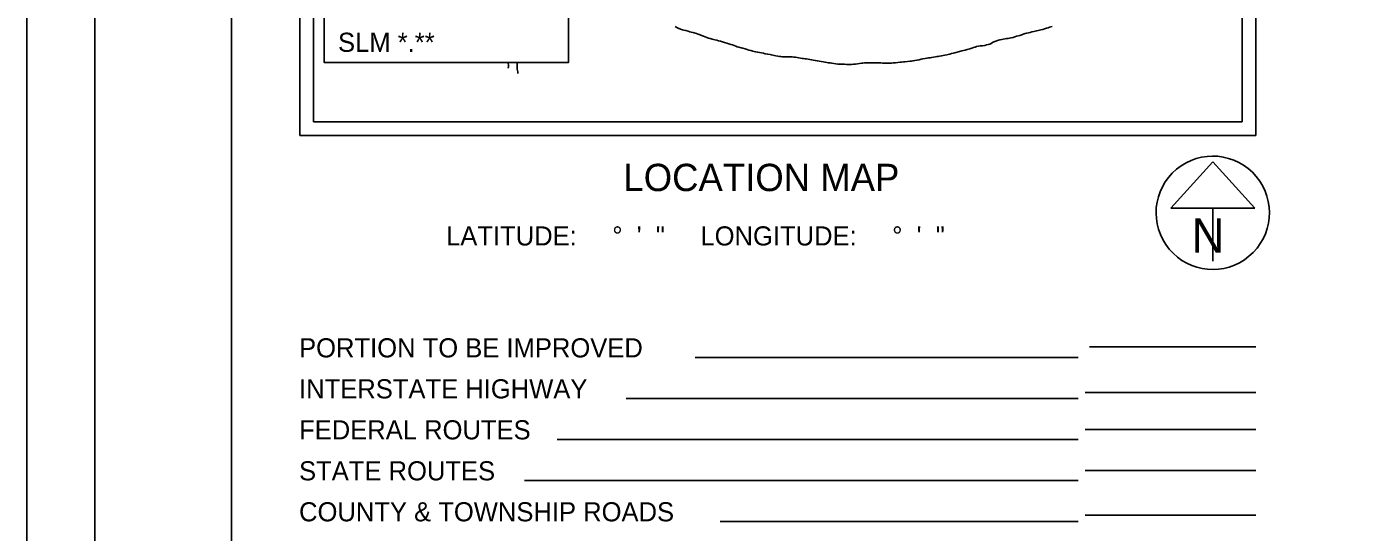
# Model space of a CAD drawing. Extents: x 0 to 34, y 0 to 22.
# Drawn here: x 0 to 9.77, y 11.1 to 14.8 of the extents above; entities that cross this region are included whole.
import ezdxf

# ---------------------------------------------------------------- set-up
doc = ezdxf.new("R2010")
doc.units = 0
for name, color, linetype in [('GM_X_Major_River', 7, 'Continuous'), ('SH_Border', 7, 'Continuous'), ('SH_Cut_Line', 7, 'Continuous'), ('SH_Data', 7, 'Continuous'), ('SH_Text', 7, 'Continuous')]:
    doc.layers.add(name, color=color, linetype=linetype)

msp = doc.modelspace()

# ---------------------------------------------------------------- linework, layer by layer
at = {"layer": 'GM_X_Major_River'}
for points in [[(4.7482, 14.7976), (4.761, 14.7915), (4.7709, 14.7874), (4.7871, 14.7801)], [(4.7871, 14.7801), (4.8015, 14.7748), (4.8121, 14.7718), (4.8261, 14.7684), (4.8423, 14.7638), (4.8556, 14.7604), (4.8666, 14.7578), (4.8783, 14.7551), (4.8885, 14.7513), (4.9036, 14.7464), (4.9172, 14.7419), (4.9316, 14.7377), (4.9414, 14.7331), (4.955, 14.7286), (4.969, 14.7233), (4.9804, 14.7187), (4.9929, 14.7142), (5.0057, 14.7096), (5.0182, 14.7058), (5.0292, 14.7028), (5.0398, 14.7001), (5.0522, 14.6975), (5.0647, 14.6945), (5.0795, 14.6907), (5.095, 14.6861), (5.1101, 14.682), (5.1275, 14.6774), (5.14, 14.6725), (5.1551, 14.6672), (5.168, 14.6634), (5.1812, 14.6596), (5.1922, 14.6547), (5.202, 14.6509), (5.2137, 14.6475), (5.2311, 14.6429), (5.2436, 14.6395), (5.2599, 14.6349), (5.2757, 14.6296), (5.2886, 14.6255), (5.3011, 14.6228), (5.3162, 14.6183), (5.3268, 14.6156), (5.3389, 14.6129), (5.3518, 14.6111), (5.3669, 14.608), (5.3813, 14.6057), (5.3941, 14.6031), (5.4077, 14.5993), (5.4259, 14.5955), (5.4429, 14.5925), (5.4535, 14.5902), (5.4645, 14.5879), (5.4747, 14.5856), (5.4849, 14.5841), (5.5008, 14.5811), (5.5121, 14.5792), (5.5231, 14.5781), (5.5329, 14.5773), (5.5443, 14.5769), (5.5567, 14.5762), (5.5681, 14.5762), (5.5783, 14.5754), (5.6044, 14.5754), (5.6173, 14.575), (5.6297, 14.5743), (5.6415, 14.5724), (5.6528, 14.5697), (5.6653, 14.5674), (5.6785, 14.5652), (5.6891, 14.564), (5.7012, 14.5625), (5.711, 14.5617), (5.7209, 14.5602), (5.7466, 14.5557), (5.7598, 14.5526), (5.7742, 14.5504), (5.7897, 14.5469), (5.8037, 14.5439), (5.8185, 14.5416), (5.8332, 14.5397), (5.8445, 14.5382), (5.8589, 14.5352), (5.8695, 14.5333), (5.8831, 14.5318), (5.8945, 14.5295), (5.9236, 14.5253), (5.9398, 14.5238), (5.9576, 14.5223), (5.9731, 14.5219), (5.9879, 14.5219), (6.0026, 14.5215), (6.0136, 14.5207), (6.0242, 14.5207), (6.0382, 14.5215), (6.0537, 14.5226), (6.0684, 14.5238), (6.0839, 14.5253), (6.0987, 14.5276), (6.1119, 14.5294), (6.1229, 14.531), (6.1342, 14.5321)], [(6.1342, 14.5321), (6.1444, 14.5329), (6.1679, 14.5336), (6.1826, 14.5336), (6.1981, 14.5332), (6.208, 14.5328), (6.2178, 14.5325), (6.2284, 14.5321), (6.2401, 14.5321), (6.2534, 14.5317), (6.2658, 14.5313), (6.2817, 14.5309), (6.2931, 14.5302), (6.3071, 14.5298), (6.3195, 14.5301), (6.3313, 14.5309), (6.3445, 14.532), (6.3611, 14.5332), (6.3785, 14.5351), (6.3948, 14.5366), (6.4065, 14.5381), (6.4198, 14.5392), (6.4303, 14.5404), (6.4496, 14.5422), (6.4685, 14.5441), (6.4791, 14.5449), (6.4893, 14.5464), (6.5026, 14.5491), (6.5181, 14.5517), (6.5347, 14.5555), (6.5502, 14.5597), (6.5616, 14.5623), (6.5778, 14.5642), (6.5911, 14.5665), (6.602, 14.5684), (6.6145, 14.5699), (6.6259, 14.5714), (6.6387, 14.5737), (6.6542, 14.5759), (6.6652, 14.5782), (6.675, 14.5793), (6.6849, 14.5816), (6.6992, 14.5839), (6.7106, 14.5862), (6.7227, 14.5884), (6.7363, 14.5911), (6.748, 14.5941), (6.7597, 14.596), (6.7722, 14.6002), (6.7843, 14.6024), (6.7949, 14.6058), (6.8123, 14.6104), (6.8305, 14.6153), (6.8482, 14.6202), (6.8607, 14.6233), (6.8724, 14.6259), (6.8868, 14.6297), (6.905, 14.6346), (6.9212, 14.6396), (6.9337, 14.6445), (6.9439, 14.6479), (6.9545, 14.6513), (6.9681, 14.6543), (6.9806, 14.657), (6.9987, 14.6581), (7.015, 14.6604), (7.029, 14.6634), (7.0411, 14.6657), (7.0524, 14.6699), (7.0623, 14.674), (7.0721, 14.6812), (7.0819, 14.6861), (7.0956, 14.6922), (7.1077, 14.6971), (7.1247, 14.7017), (7.1391, 14.704), (7.1508, 14.7058), (7.164, 14.7077), (7.1746, 14.71), (7.1875, 14.7119), (7.2071, 14.7149), (7.2234, 14.7187), (7.2359, 14.7229), (7.248, 14.7267), (7.2616, 14.7301), (7.2718, 14.7339), (7.2854, 14.738), (7.2956, 14.7414), (7.3111, 14.7464), (7.3228, 14.7502), (7.3357, 14.7528), (7.3467, 14.7555), (7.3603, 14.7585), (7.3735, 14.7611), (7.3841, 14.7642), (7.3951, 14.7664), (7.4068, 14.7691), (7.4257, 14.7733), (7.4401, 14.7778), (7.4533, 14.7827), (7.4662, 14.7861)], [(7.4662, 14.7861), (7.479, 14.7892), (7.4904, 14.793), (7.5082, 14.7986)], [(3.5253, 14.5355), (3.5259, 14.5299), (3.5274, 14.5144), (3.5274, 14.5049), (3.5263, 14.4943)], [(3.5958, 14.4552), (3.5951, 14.4658), (3.5939, 14.4757), (3.5921, 14.4859), (3.5902, 14.4992), (3.5909, 14.5121), (3.5921, 14.5261), (3.5937, 14.5355)]]:
    msp.add_lwpolyline(points, dxfattribs=at)
at = {"layer": 'SH_Border'}
for points in [[(0.5, 21.5), (1.5, 21.5), (1.5, 0.5), (0.5, 0.5)], [(1.5, 21.5), (33.5, 21.5), (33.5, 0.5), (1.5, 0.5)]]:
    msp.add_lwpolyline(points, close=True, dxfattribs=at)
at = {"layer": 'SH_Cut_Line'}
msp.add_lwpolyline([(0, 0), (34, 0), (34, 22), (0, 22)], close=True, dxfattribs=at)
at = {"layer": 'SH_Data'}
for p, q in [((2, 21), (2, 14)), ((9, 21), (9, 14)), ((2.1, 20.9), (2.1, 14.1)), ((8.9, 20.9), (8.9, 14.1)), ((2.1, 14.1), (8.9, 14.1)), ((2.1, 14.1), (2.1, 14.1)), ((2, 14), (9, 14)), ((8.6845, 13.8091), (8.3769, 13.4678)), ((8.9921, 13.4678), (8.6845, 13.8091)), ((8.3769, 13.4678), (8.9921, 13.4678)), ((8.6845, 13.4678), (8.6845, 13.0811)), ((8.6845, 13.4353), (8.6845, 13.4353)), ((8.6845, 13.4353), (8.6845, 13.4353)), ((7.7827, 12.4553), (9, 12.4553)), ((7.7, 12.3767), (4.8937, 12.3767)), ((9, 12.1207), (7.75, 12.1207)), ((7.7, 12.0767), (4.3895, 12.0767)), ((9, 11.8491), (7.75, 11.8491)), ((7.7, 11.7767), (3.8854, 11.7767)), ((9, 11.5491), (7.75, 11.5491)), ((7.7, 11.4767), (3.6448, 11.4767)), ((7.7, 11.1767), (5.0782, 11.1767)), ((9, 11.2223), (7.75, 11.2223))]:
    msp.add_line(p, q, dxfattribs=at)
msp.add_arc((8.6845, 13.4353), 0.4148, 129.77984, 129.76332, dxfattribs=at)
at = {"layer": 'SH_Text'}
msp.add_lwpolyline([(2.178, 15.2507), (3.9674, 15.2507), (3.9674, 14.5355), (2.178, 14.5355)], close=True, dxfattribs=at)

# ---------------------------------------------------------------- texts
at = {"layer": 'SH_Data'}
msp.add_text('N', height=0.25, dxfattribs=at).set_placement((8.5292, 13.144))
at = {"layer": 'SH_Text'}
for s, height, p in [('SLM *.**', 0.14, (2.2797, 14.6131)), ('LOCATION MAP', 0.2, (4.3691, 13.5938)), ('LATITUDE:     °  \'  "     LONGITUDE:     °  \'  "', 0.14, (3.071, 13.1959)), ('PORTION TO BE IMPROVED', 0.14, (1.9944, 12.3767)), ('INTERSTATE HIGHWAY', 0.14, (1.9944, 12.0767)), ('FEDERAL ROUTES', 0.14, (1.9944, 11.7767)), ('STATE ROUTES', 0.14, (1.9944, 11.4767)), ('COUNTY & TOWNSHIP ROADS', 0.14, (1.9944, 11.1767))]:
    msp.add_text(s, height=height, dxfattribs=at).set_placement(p)

doc.saveas('drawing.dxf')
